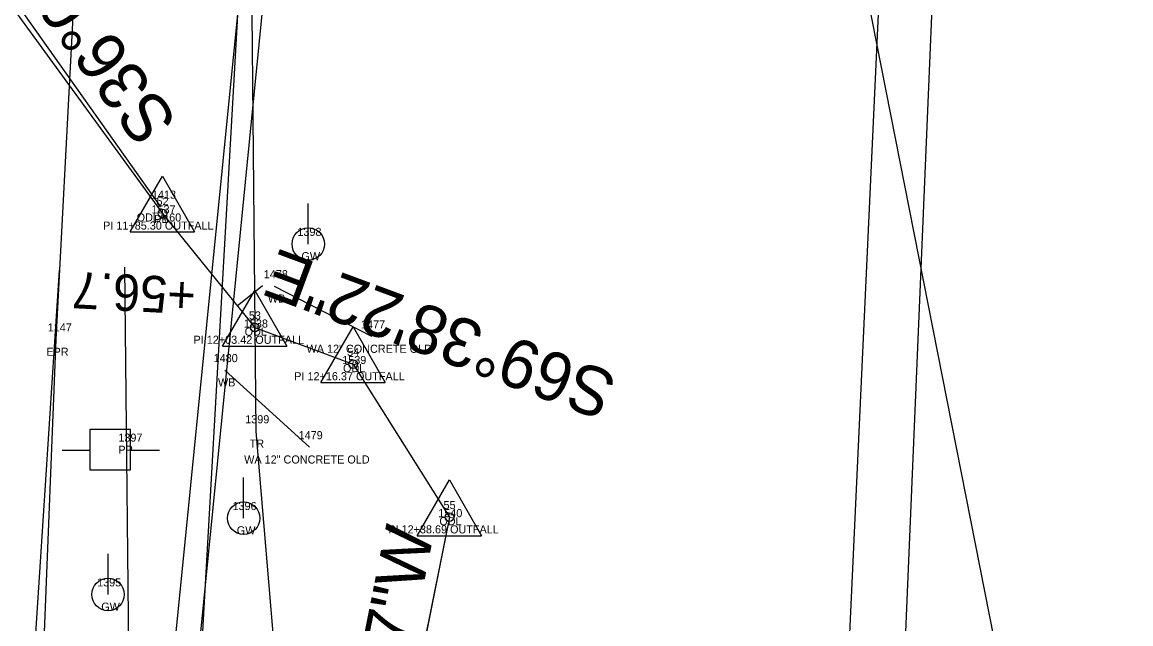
# Model space of a CAD drawing. Extents: x 1812113 to 1819860, y 1177290 to 1181185.
# Drawn here: x 1813680.6 to 1813817.4, y 1178865.2 to 1178939.4 of the extents above; entities that cross this region are included whole.
import ezdxf

# ---------------------------------------------------------------- set-up
doc = ezdxf.new("R2010")
doc.units = 0
for name, color, linetype in [('RD_EX_BldgApp', 7, 'Continuous'), ('RD_EX_BldgApp_txCode', 7, 'Continuous'), ('RD_EX_DR_Pipe', 7, 'Continuous'), ('RD_EX_DR_Pipe_txCode', 7, 'Continuous'), ('RD_EX_H2O', 7, 'Continuous'), ('RD_EX_H2O_txCode', 7, 'Continuous'), ('RD_EX_Misc', 7, 'Continuous'), ('RD_EX_Road', 7, 'Continuous'), ('RD_EX_Road_txCode', 7, 'Continuous'), ('RD_EX_RW', 7, 'Continuous'), ('RD_EX_UT', 7, 'Continuous'), ('RD_EX_UT_txCode', 7, 'Continuous'), ('RD_EX_VEG', 7, 'Continuous'), ('RD_EX_VEG_txCode', 7, 'Continuous'), ('RD_HC_CL', 7, 'Continuous'), ('RD_HC_Data', 7, 'Continuous'), ('RD_HC_Data_Tic', 7, 'Continuous'), ('RD_HC_txCode', 7, 'Continuous'), ('RD_PD_ALT1_TnTmp', 7, 'Continuous'), ('RD_PD_ALT1_TrvlWay', 7, 'Continuous'), ('RD_PD_CstnLmt', 7, 'Continuous'), ('RD_PD_DR_ErosCtrl', 7, 'Continuous'), ('RD_PD_PatLn1', 7, 'Continuous'), ('RD_SMD_Locator', 7, 'Continuous')]:
    doc.layers.add(name, color=color, linetype=linetype)

msp = doc.modelspace()

# ---------------------------------------------------------------- linework, layer by layer
at = {"layer": 'RD_EX_BldgApp'}
for p, q in [((1813723.78, 1178900.65), (1813711.77, 1178906.85)), ((1813716.08, 1178886.99), (1813705.63, 1178896.5))]:
    msp.add_line(p, q, dxfattribs=at)
at = {"layer": 'RD_EX_DR_Pipe'}
msp.add_line((1813650.55, 1178983.27), (1813697.68, 1178916.66), dxfattribs=at)
at = {"layer": 'RD_EX_H2O'}
msp.add_lwpolyline([(1813697.92, 1178915.85), (1813709.32, 1178901.76), (1813721.45, 1178897.26), (1813733.34, 1178878.37), (1813728.06, 1178852.05), (1813743.31, 1178836.1), (1813784.4, 1178814.3)], dxfattribs=at)
at = {"layer": 'RD_EX_Misc'}
for points in [[(1813405.71, 1178572.74), (1813779.17, 1178786.7), (1813799.35, 1179222.21)], [(1813408.47, 1178567.92), (1813786.33, 1178785.29), (1813804.76, 1179221.83)]]:
    msp.add_lwpolyline(points, dxfattribs=at)
at = {"layer": 'RD_EX_Road'}
for p, q in [((1813684.82, 1178900.28), (1813687.23, 1178946.66)), ((1813682.76, 1178849.48), (1813684.82, 1178900.28))]:
    msp.add_line(p, q, dxfattribs=at)
at = {"layer": 'RD_EX_RW'}
msp.add_line((1813698.67, 1178789.48), (1813713.48, 1179050.77), dxfattribs=at)
at = {"layer": 'RD_EX_UT'}
for p, q in [((1813715.92, 1178912.07), (1813715.92, 1178917.07)), ((1813693.98, 1178889.2), (1813688.98, 1178889.2)), ((1813688.98, 1178889.2), (1813688.98, 1178884.2)), ((1813693.98, 1178884.2), (1813693.98, 1178889.2)), ((1813685.54, 1178886.64), (1813689.01, 1178886.64)), ((1813693.9, 1178886.64), (1813697.54, 1178886.64)), ((1813688.98, 1178884.2), (1813693.98, 1178884.2)), ((1813707.94, 1178878.25), (1813707.94, 1178883.25)), ((1813691.21, 1178868.83), (1813691.21, 1178873.83))]:
    msp.add_line(p, q, dxfattribs=at)
msp.add_lwpolyline([(1813817.45, 1178777.9), (1813754.12, 1179098.9), (1813749.26, 1179176.64)], dxfattribs=at)
for centre in [(1813715.92, 1178912.07), (1813707.94, 1178878.25), (1813691.21, 1178868.83)]:
    msp.add_circle(centre, 2, dxfattribs=at)
at = {"layer": 'RD_EX_VEG'}
msp.add_lwpolyline([(1813748.11, 1178842.01), (1813712.02, 1178859.16), (1813709.48, 1178888.95), (1813708.93, 1178949.18), (1813715.24, 1179043.86)], dxfattribs=at)
at = {"layer": 'RD_HC_CL'}
for p, q in [((1813650.05, 1178981.56), (1813697.92, 1178915.85)), ((1813697.92, 1178915.85), (1813709.32, 1178901.76)), ((1813709.32, 1178901.76), (1813721.45, 1178897.26)), ((1813721.45, 1178897.26), (1813733.34, 1178878.37)), ((1813733.34, 1178878.37), (1813728.06, 1178852.05))]:
    msp.add_line(p, q, dxfattribs=at)
at = {"layer": 'RD_HC_Data'}
for p, q in [((1813693.95, 1178913.56), (1813697.92, 1178920.44)), ((1813697.92, 1178920.44), (1813701.89, 1178913.56)), ((1813693.95, 1178913.56), (1813701.89, 1178913.56)), ((1813705.35, 1178899.47), (1813709.32, 1178906.35)), ((1813709.32, 1178906.35), (1813713.29, 1178899.47)), ((1813717.48, 1178894.97), (1813721.46, 1178901.85)), ((1813721.46, 1178901.85), (1813725.42, 1178894.97)), ((1813705.35, 1178899.47), (1813713.29, 1178899.47)), ((1813717.48, 1178894.97), (1813725.42, 1178894.97)), ((1813729.37, 1178876.08), (1813733.34, 1178882.96)), ((1813733.34, 1178882.96), (1813737.31, 1178876.08)), ((1813729.37, 1178876.08), (1813737.31, 1178876.08))]:
    msp.add_line(p, q, dxfattribs=at)
for centre in [(1813697.92, 1178915.85), (1813709.32, 1178901.76), (1813721.45, 1178897.26), (1813733.34, 1178878.37)]:
    msp.add_circle(centre, 0.529, dxfattribs=at)
at = {"layer": 'RD_HC_Data_Tic'}
msp.add_line((1813707.16, 1178904.43), (1813710.27, 1178906.94), dxfattribs=at)
at = {"layer": 'RD_PD_ALT1_TrvlWay'}
msp.add_line((1813678.74, 1178809.04), (1813685.22, 1178908.83), dxfattribs=at)
at = {"layer": 'RD_PD_CstnLmt'}
msp.add_line((1813698.35, 1178851.3), (1813708.26, 1178950.9), dxfattribs=at)
at = {"layer": 'RD_PD_DR_ErosCtrl'}
msp.add_line((1813701.35, 1178851.13), (1813711.25, 1178950.73), dxfattribs=at)
at = {"layer": 'RD_PD_PatLn1'}
msp.add_line((1813693.85, 1178853.27), (1813693.3, 1178909.23), dxfattribs=at)
at = {"layer": 'RD_SMD_Locator'}
for centre in [(1813697.68, 1178916.66), (1813697.92, 1178915.85), (1813697.92, 1178915.85), (1813711.77, 1178906.85), (1813709.32, 1178901.76), (1813709.32, 1178901.76), (1813684.82, 1178900.28), (1813723.78, 1178900.65), (1813705.63, 1178896.5), (1813721.45, 1178897.26), (1813721.45, 1178897.26), (1813709.48, 1178888.95), (1813716.08, 1178886.99), (1813733.34, 1178878.37), (1813733.34, 1178878.37)]:
    msp.add_circle(centre, 0.001, dxfattribs=at)

# ---------------------------------------------------------------- texts
at = {"layer": 'RD_EX_BldgApp_txCode'}
for s, p in [('1478', (1813710.43, 1178907.85)), ('WB', (1813710.93, 1178904.85)), ('1477', (1813722.43, 1178901.65)), ('WA 12" CONCRETE OLD', (1813715.71, 1178898.65)), ('1480', (1813704.24, 1178897.5)), ('WB', (1813704.78, 1178894.5)), ('1479', (1813714.73, 1178887.99)), ('WA 12" CONCRETE OLD', (1813708.01, 1178884.99))]:
    msp.add_text(s, height=1, dxfattribs=at).set_placement(p)
at = {"layer": 'RD_EX_DR_Pipe_txCode'}
for s, p in [('1413', (1813696.62, 1178917.66)), ('PB', (1813696.9, 1178914.66))]:
    msp.add_text(s, height=1, dxfattribs=at).set_placement(p)
at = {"layer": 'RD_EX_H2O_txCode'}
for s, p in [('1537', (1813696.57, 1178915.85)), ('ODLA 60', (1813694.74, 1178914.85)), ('1538', (1813707.97, 1178901.76)), ('ODL', (1813708.07, 1178900.76)), ('1539', (1813720.11, 1178897.26)), ('ODL', (1813720.21, 1178896.26)), ('1540', (1813731.96, 1178878.37)), ('ODL', (1813732.1, 1178877.37))]:
    msp.add_text(s, height=1, dxfattribs=at).set_placement(p)
at = {"layer": 'RD_EX_Road_txCode'}
for s, p in [('1147', (1813683.76, 1178901.28)), ('EPR', (1813683.59, 1178898.28))]:
    msp.add_text(s, height=1, dxfattribs=at).set_placement(p)
at = {"layer": 'RD_EX_UT_txCode'}
for s, p in [('1398', (1813714.58, 1178913.07)), ('GW', (1813715.08, 1178910.07)), ('1397', (1813692.48, 1178887.69)), ('PP', (1813692.48, 1178886.19)), ('1396', (1813706.57, 1178879.25)), ('GW', (1813707.1, 1178876.25)), ('1395', (1813689.86, 1178869.83)), ('GW', (1813690.37, 1178866.83))]:
    msp.add_text(s, height=1, dxfattribs=at).set_placement(p)
at = {"layer": 'RD_EX_VEG_txCode'}
for s, p in [('1399', (1813708.14, 1178889.95)), ('TR', (1813708.69, 1178886.95))]:
    msp.add_text(s, height=1, dxfattribs=at).set_placement(p)
at = {"layer": 'RD_HC_txCode'}
for s, p in [('52', (1813697.19, 1178916.85)), ('PI 11+85.30 OUTFALL', (1813690.6, 1178913.85)), ('53', (1813708.59, 1178902.76)), ('PI 12+03.42 OUTFALL', (1813701.76, 1178899.76)), ('54', (1813720.72, 1178898.26)), ('PI 12+16.37 OUTFALL', (1813714.19, 1178895.26)), ('55', (1813732.61, 1178879.37)), ('PI 12+38.69 OUTFALL', (1813725.8, 1178876.37))]:
    msp.add_text(s, height=1, dxfattribs=at).set_placement(p)
at = {"layer": 'RD_PD_ALT1_TnTmp'}
for s, rotation, p in [('S36%%d04\'29"E', 126.0747, (1813699.95, 1178927.2)), ('S69%%d38\'22"E', 159.6395, (1813754.33, 1178895.88)), ('S11%%d20\'47"W', 78.6536, (1813722.16, 1178830.14))]:
    msp.add_text(s, height=6, rotation=rotation, dxfattribs=at).set_placement(p)
at = {"layer": 'RD_PD_ALT1_TrvlWay'}
msp.add_text('+56.7', height=4.5, rotation=177.0283, dxfattribs=at).set_placement((1813702.14, 1178907.87))

doc.saveas('drawing.dxf')
